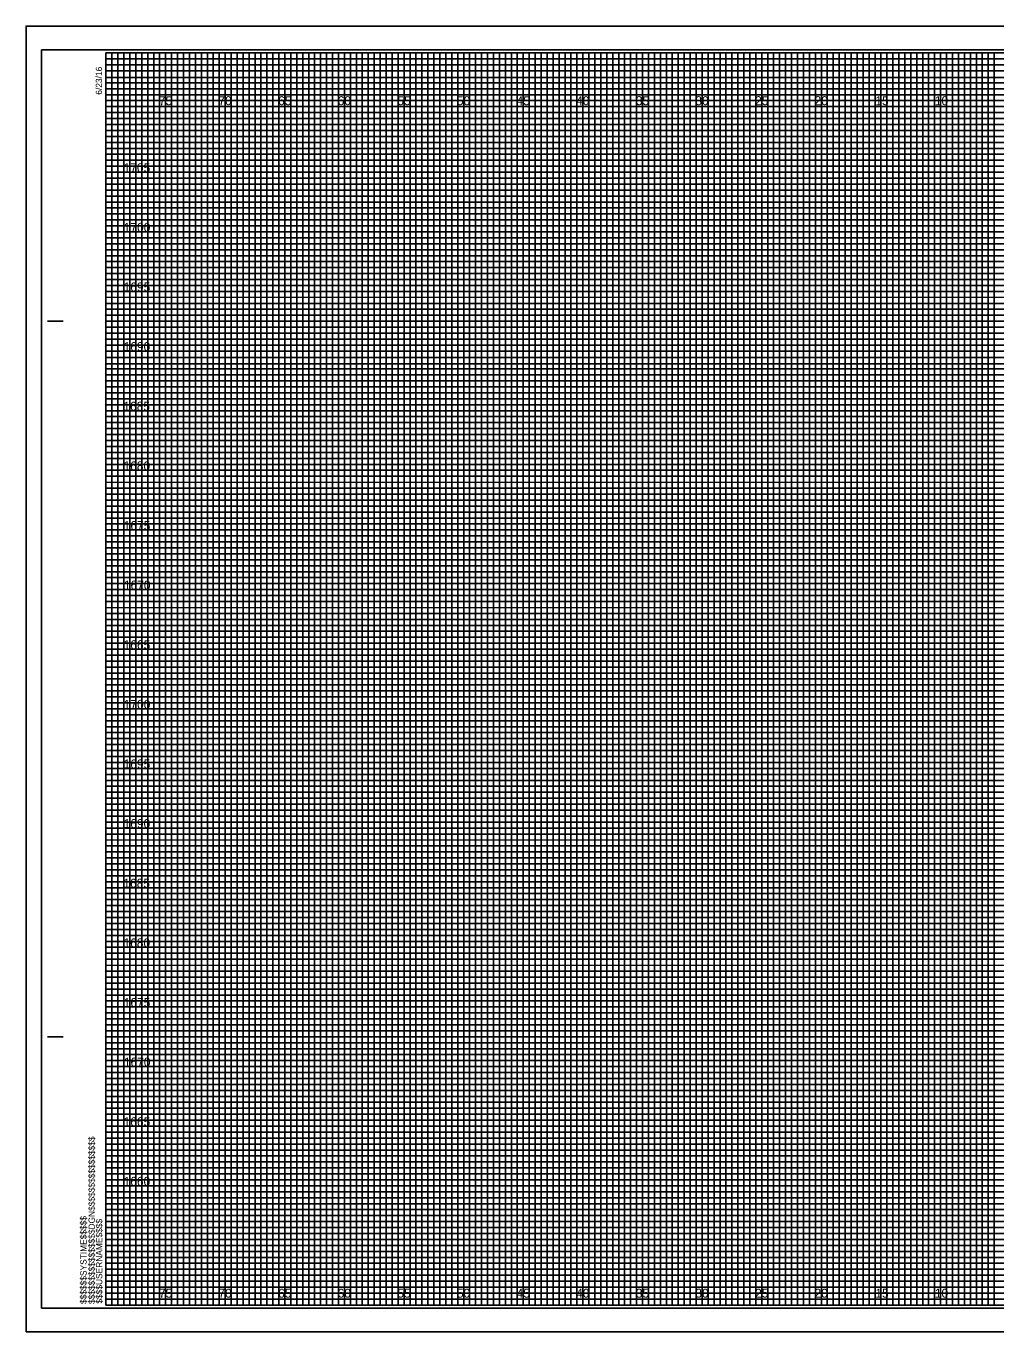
# Model space of a CAD drawing. Extents: x -7 to 162, y -2 to 217.
# Drawn here: x -6.7 to 74.6, y -2.3 to 107.3 of the extents above; entities that cross this region are included whole.
import ezdxf

# ---------------------------------------------------------------- set-up
doc = ezdxf.new("R2010")
doc.units = 0
for name, color, linetype in [('Prop XS Elevation Labels', 7, 'Continuous'), ('Prop XS Offset Labels', 7, 'Continuous'), ('Sheet Cross Section CELL', 7, 'Continuous'), ('Sheet Cross Section Grid Major CELL', 7, 'Continuous'), ('Sheet Cross Section Grid Middle CELL', 7, 'Continuous'), ('Sheet Cross Section Grid Minor 1 CELL', 7, 'Continuous'), ('Sheet Cross Section Grid Minor 2 CELL', 7, 'Continuous'), ('Sheet Cutting Line CELL', 7, 'Continuous'), ('Sheet DOT Grid CELL', 7, 'Continuous'), ('Sheet Plot Border Inside CELL', 7, 'Continuous'), ('Sheet Plot Border Outside CELL', 7, 'Continuous')]:
    doc.layers.add(name, color=color, linetype=linetype)

msp = doc.modelspace()

# ---------------------------------------------------------------- linework, layer by layer
at = {"layer": 'Sheet Cross Section CELL'}
for p, q in [((-4.9, 82.5), (-3.65, 82.5)), ((-4.85, 82.5), (-3.6, 82.5)), ((-4.9, 22.5), (-3.65, 22.5)), ((-4.85, 22.5), (-3.6, 22.5)), ((0, 0), (0, 0)), ((0, 0), (0, 0)), ((0, 0), (0, 0)), ((0, 0), (0, 0)), ((0, 0), (0, 0)), ((0, 0), (0, 0)), ((0, 0), (0, 0))]:
    msp.add_line(p, q, dxfattribs=at)
msp.add_lwpolyline([(160, 105), (0, 105), (0, 0), (160, 0)], close=True, dxfattribs=at)
at = {"layer": 'Sheet Cross Section Grid Major CELL'}
for p, q in [((5, 105), (0, 105)), ((5, 0), (5, 105)), ((15, 105), (10, 105)), ((10, 105), (10, 0)), ((15, 0), (15, 105)), ((25, 105), (20, 105)), ((20, 105), (20, 0)), ((25, 0), (25, 105)), ((35, 105), (30, 105)), ((30, 105), (30, 0)), ((35, 0), (35, 105)), ((45, 105), (40, 105)), ((40, 105), (40, 0)), ((45, 0), (45, 105)), ((55, 105), (50, 105)), ((50, 105), (50, 0)), ((55, 0), (55, 105)), ((65, 105), (60, 105)), ((60, 105), (60, 0)), ((65, 0), (65, 105)), ((75, 105), (70, 105)), ((70, 105), (70, 0)), ((10, 0), (5, 0)), ((20, 0), (15, 0)), ((30, 0), (25, 0)), ((40, 0), (35, 0)), ((50, 0), (45, 0)), ((60, 0), (55, 0)), ((70, 0), (65, 0))]:
    msp.add_line(p, q, dxfattribs=at)
for points in [[(0, 100), (160, 100), (160, 95), (0, 95)], [(0, 90), (160, 90), (160, 85), (0, 85)], [(0, 80), (160, 80), (160, 75), (0, 75)], [(0, 70), (160, 70), (160, 65), (0, 65)], [(0, 60), (160, 60), (160, 55), (0, 55)], [(0, 50), (160, 50), (160, 45), (0, 45)], [(0, 40), (160, 40), (160, 35), (0, 35)], [(0, 30), (160, 30), (160, 25), (0, 25)], [(0, 20), (160, 20), (160, 15), (0, 15)], [(0, 10), (160, 10), (160, 5), (0, 5)]]:
    msp.add_lwpolyline(points, dxfattribs=at)
at = {"layer": 'Sheet Cross Section Grid Middle CELL'}
for points in [[(0, 105), (2.5, 105), (2.5, 0), (7.5, 0), (7.5, 105), (12.5, 105), (12.5, 0), (17.5, 0), (17.5, 105), (22.5, 105), (22.5, 0), (27.5, 0), (27.5, 105), (32.5, 105), (32.5, 0), (37.5, 0), (37.5, 105), (42.5, 105), (42.5, 0), (47.5, 0), (47.5, 105), (52.5, 105), (52.5, 0), (57.5, 0), (57.5, 105), (62.5, 105), (62.5, 0), (67.5, 0), (67.5, 105), (72.5, 105), (72.5, 0), (77.5, 0)], [(0, 102.5), (137.5, 102.5)], [(0, 92.5), (160, 92.5), (160, 97.5), (0, 97.5)], [(0, 82.5), (160, 82.5), (160, 87.5), (0, 87.5)], [(0, 72.5), (160, 72.5), (160, 77.5), (0, 77.5)], [(0, 62.5), (160, 62.5), (160, 67.5), (0, 67.5)], [(0, 52.5), (160, 52.5), (160, 57.5), (0, 57.5)], [(0, 42.5), (160, 42.5), (160, 47.5), (0, 47.5)], [(0, 32.5), (160, 32.5), (160, 37.5), (0, 37.5)], [(0, 22.5), (160, 22.5), (160, 27.5), (0, 27.5)], [(0, 12.5), (160, 12.5), (160, 17.5), (0, 17.5)], [(0, 2.5), (160, 2.5), (160, 7.5), (0, 7.5)]]:
    msp.add_lwpolyline(points, dxfattribs=at)
at = {"layer": 'Sheet Cross Section Grid Minor 1 CELL'}
for p, q in [((0, 104.5), (130, 104.5)), ((130, 103.99), (0, 103.99)), ((0, 103.99), (0, 103.5)), ((0, 103.5), (130, 103.5)), ((130, 102.95), (0, 102.95)), ((0, 102.95), (0, 102)), ((0, 102), (160, 102))]:
    msp.add_line(p, q, dxfattribs=at)
for points in [[(0, 101.5), (135, 101.5), (160, 101.5), (160, 101), (0, 101)], [(0, 100.5), (160, 100.5), (160, 99.5), (0, 99.5)], [(0, 99), (160, 99), (160, 98.5), (0, 98.49)], [(0, 98), (160, 98), (160, 97), (0, 97)], [(0, 96.5), (160, 96.5), (160, 96), (0, 96)], [(0, 95.5), (160, 95.5), (160, 94.5), (0, 94.5)], [(0, 94), (160, 94), (160, 93.5), (0, 93.5)], [(0, 93), (160, 93), (160, 92), (0, 92)], [(0, 91.5), (160, 91.5), (160, 91), (0, 91)], [(0, 90.5), (160, 90.5), (160, 89.5), (0, 89.5)], [(0, 89), (160, 89), (160, 88.5), (0, 88.5)], [(0, 88), (160, 88), (160, 86.98), (160, 86.5), (160, 86), (0, 86)], [(0, 87), (160, 87), (160, 86.5), (0, 86.5)], [(0, 85.5), (160, 85.5), (160, 84.5), (0, 84.52)], [(0, 84.52), (160, 84.5), (160, 84), (0, 84)], [(0, 83.5), (160, 83.5), (160, 83), (0, 83)], [(0, 82), (160, 82), (160, 81.5), (0, 81.5)], [(0, 81), (160, 81), (160, 80.5), (0, 80.5)], [(-0.04, 79.45), (160, 79.45), (160, 78.94), (-0.04, 78.94)], [(0, 78.5), (160, 78.5), (160, 78), (0, 78)], [(0, 77), (160, 77), (160, 76.5), (0, 76.5)], [(0, 76), (160, 76), (160, 75.5), (0, 75.5)], [(0, 74.5), (160, 74.5), (160, 74), (0, 74)], [(0, 73.5), (160, 73.5), (160, 73), (0, 73)], [(0, 72), (160, 72), (160, 71.5), (0, 71.5)], [(0, 71), (160, 71), (160, 70.5), (0, 70.5)], [(0, 69.5), (160, 69.5), (160, 68.99), (0, 69)], [(0, 68.5), (160, 68.5), (160, 68), (0, 68)], [(0, 67), (160, 67), (160, 66.5), (0, 66.5)], [(0, 66), (160, 66), (160, 65.5), (0, 65.5)], [(0, 64.5), (160, 64.5), (160, 64), (0, 64)], [(0, 63.5), (160, 63.5), (160, 63), (0, 63)], [(0, 62), (160, 62), (160, 61.5), (0, 61.5)], [(0, 61), (160, 61), (160, 60.5), (0, 60.5)], [(0, 59.5), (160, 59.5), (160, 59), (0, 59)], [(0, 58.5), (160.03, 58.45), (160, 58), (0, 58)], [(0, 57), (160, 57), (160, 56.5), (0, 56.5)], [(0, 56), (160, 56), (160, 55.5), (0, 55.5)], [(0, 54.5), (160, 54.5), (160, 54), (0, 54)], [(0, 53.5), (160, 53.5), (160, 53), (0, 53)], [(0, 52), (160, 52), (160, 51.5), (0, 51.5)], [(0, 51), (160, 51), (160, 50.5), (0, 50.5)], [(0, 49.5), (160, 49.5), (160, 49), (0, 49)], [(0, 48.5), (160, 48.5), (160, 48), (0, 48)], [(0, 47), (160, 47), (160, 46.5), (0, 46.5)], [(0, 46), (160, 46), (160, 45.5), (0, 45.5)], [(0, 44.5), (160, 44.5), (160, 44), (0, 44)], [(0, 43.5), (160, 43.5), (160, 43), (0, 43)], [(0, 42), (160, 42), (160, 41.5), (0, 41.5)], [(0, 41), (160, 41), (160, 40.5), (0, 40.5)], [(0, 39.5), (160, 39.5), (160, 38.99), (0, 39)], [(0, 38.5), (160, 38.5), (160, 38), (0, 38)], [(0, 37), (160, 37), (160, 36.5), (0, 36.5)], [(0, 36), (160, 36), (160, 35.5), (0, 35.5)], [(0, 34.5), (160, 34.5), (160, 34), (0, 34)], [(0, 33.5), (160, 33.5), (160, 33), (0, 33)], [(0, 32), (160, 32), (160, 31.5), (0, 31.5)], [(0, 31), (160, 31), (160, 30.5), (0, 30.5)], [(0, 29.5), (160, 29.5), (160, 29), (0, 29)], [(0, 28.5), (160.03, 28.46), (160, 28), (0, 28)], [(0, 27), (160, 27), (160, 26.5), (0, 26.5)], [(0, 26), (160, 26), (160, 25.5), (0, 25.5)], [(0, 24.5), (160, 24.5), (160, 24), (0, 24)], [(0, 23.5), (160, 23.5), (160, 23), (0, 23)], [(0, 22), (160, 22), (160, 21.5), (0, 21.5)], [(0, 21), (160, 21), (160, 20.5), (0, 20.5)], [(0, 19.5), (160, 19.5), (160, 19), (0, 19)], [(0, 18.5), (160, 18.5), (160, 18), (0, 18)], [(0, 17), (160, 17), (160, 16.5), (0, 16.5)], [(0, 16), (160, 16), (160, 15.5), (0, 15.5)], [(0, 14.5), (160, 14.5), (160, 14), (0, 14)], [(0, 13.5), (160, 13.5), (160, 13), (0, 13)], [(0, 12), (160, 12), (160, 11.5), (0, 11.5)], [(0, 11), (160, 11), (160, 10.5), (0, 10.5)], [(0, 9.5), (160, 9.5), (160, 9), (0, 9)], [(0, 8.5), (160, 8.5), (160, 8), (0, 8)], [(0, 7), (160, 7), (160, 6.5), (0, 6.5)], [(0, 6), (160, 6), (160, 5.5), (0, 5.5)], [(0, 4.5), (160, 4.5), (160, 4), (0, 4)], [(0, 3.5), (160, 3.5), (160, 3), (0, 3)], [(0, 2), (160, 2), (160, 1.5), (0, 1.5)], [(0, 1), (160, 1), (160, 0.5), (0, 0.5)]]:
    msp.add_lwpolyline(points, dxfattribs=at)
at = {"layer": 'Sheet Cross Section Grid Minor 2 CELL'}
for points in [[(0, 0), (0.5, 0), (0.5, 105), (1, 105), (1, 0)], [(1, 0), (1.5, 0), (1.5, 105), (2, 105), (2, 0)], [(2.5, 0), (3, 0), (3, 105), (3.5, 105), (3.5, 0)], [(3.5, 0), (4, 0), (4, 105), (4.5, 105), (4.5, 0)], [(5, 0), (5.5, 0), (5.5, 105), (6, 105), (6, 0)], [(6, 0), (6.5, 0), (6.5, 105), (7, 105), (7, 0)], [(7.5, 0), (8, 0), (8, 105), (8.5, 105), (8.5, 0)], [(8.5, 0), (9, 0), (9, 105), (9.5, 105), (9.5, 0)], [(10, 0), (10.5, 0), (10.5, 105), (11, 105), (11, 0)], [(11, 0), (11.5, 0), (11.5, 105), (12, 105), (12, 0)], [(12.5, 0), (13, 0), (13, 105), (13.5, 105), (13.5, 0)], [(13.5, 0), (14, 0), (14, 105), (14.5, 105), (14.5, 0)], [(15, 0), (15.5, 0), (15.5, 105), (16, 105), (16, 0)], [(16, 0), (16.5, 0), (16.5, 105), (17, 105), (17, 0)], [(17.5, 0), (18, 0), (18, 105), (18.5, 105), (18.5, 0)], [(18.5, 0), (19, 0), (19, 105), (19.5, 105), (19.5, 0)], [(20, 0), (20.5, 0), (20.5, 105), (21, 105), (21, 0)], [(21, 0), (21.5, 0), (21.5, 105), (22, 105), (22, 0)], [(22.5, 0), (23, 0), (23, 105), (23.5, 105), (23.5, 0)], [(23.5, 0), (24, 0), (24, 105), (24.5, 105), (24.5, 0)], [(25, 0), (25.5, 0), (25.5, 105), (26, 105), (26, 0)], [(26, 0), (26.5, 0), (26.5, 105), (27, 105), (27, 0)], [(27.5, 0), (28, 0), (28, 105), (28.5, 105), (28.5, 0)], [(28.5, 0), (29, 0), (29, 105), (29.5, 105), (29.5, 0)], [(30, 0), (30.5, 0), (30.5, 105), (31, 105), (31, 0)], [(31, 0), (31.5, 0), (31.5, 105), (32, 105), (32, 0)], [(32.5, 0), (33, 0), (33, 105), (33.5, 105), (33.5, 0)], [(33.5, 0), (34, 0), (34, 105), (34.5, 105), (34.5, 0)], [(35, 0), (35.5, 0), (35.5, 105), (36, 105), (36, 0)], [(36, 0), (36.5, 0), (36.5, 105), (37, 105), (37, 0)], [(37.5, 0), (38, 0), (38, 105), (38.5, 105), (38.5, 0)], [(38.5, 0), (39, 0), (39, 105), (39.5, 105), (39.5, 0)], [(40, 0), (40.5, 0), (40.5, 105), (41, 105), (41, 0)], [(41, 0), (41.5, 0), (41.5, 105), (42, 105), (42, 0)], [(42.5, 0), (43, 0), (43, 105), (43.5, 105), (43.5, 0)], [(43.5, 0), (44, 0), (44, 105), (44.5, 105), (44.5, 0)], [(45, 0), (45.5, 0), (45.5, 105), (46, 105), (46, 0)], [(46, 0), (46.5, 0), (46.5, 105), (47, 105), (47, 0)], [(47.5, 0), (48, 0), (48, 105), (48.5, 105), (48.5, 0)], [(48.5, 0), (49, 0), (49, 105), (49.5, 105), (49.5, 0)], [(50, 0), (50.5, 0), (50.5, 105), (51, 105), (51, 0)], [(51, 0), (51.5, 0), (51.5, 105), (52, 105), (52, 0)], [(52.5, 0), (53, 0), (53, 105), (53.5, 105), (53.5, 0)], [(53.5, 0), (54, 0), (54, 105), (54.5, 105), (54.5, 0)], [(55, 0), (55.5, 0), (55.5, 105), (56, 105), (56, 0)], [(56, 0), (56.5, 0), (56.5, 105), (57, 105), (57, 0)], [(57.5, 0), (58, 0), (58, 105), (58.5, 105), (58.5, 0)], [(58.5, 0), (59, 0), (59, 105), (59.5, 105), (59.5, 0)], [(60, 0), (60.5, 0), (60.5, 105), (61, 105), (61, 0)], [(61, 0), (61.5, 0), (61.5, 105), (62, 105), (62, 0)], [(62.5, 0), (63, 0), (63, 105), (63.5, 105), (63.5, 0)], [(63.5, 0), (64, 0), (64, 105), (64.5, 105), (64.5, 0)], [(65, 0), (65.5, 0), (65.5, 105), (66, 105), (66, 0)], [(66, 0), (66.5, 0), (66.5, 105), (67, 105), (67, 0)], [(67.5, 0), (68, 0), (68, 105), (68.5, 105), (68.5, 0)], [(68.5, 0), (69, 0), (69, 105), (69.5, 105), (69.5, 0)], [(70, 0), (70.5, 0), (70.5, 105), (71, 105), (71, 0)], [(71, 0), (71.5, 0), (71.5, 105), (72, 105), (72, 0)], [(72.5, 0), (73, 0), (73, 105), (73.5, 105), (73.5, 0)], [(73.5, 0), (74, 0), (74, 105), (74.5, 105), (74.5, 0)]]:
    msp.add_lwpolyline(points, dxfattribs=at)
at = {"layer": 'Sheet Cutting Line CELL'}
for p, q in [((161.65, 107.25), (-6.7, 107.25)), ((-6.7, 107.25), (-6.7, -2.25)), ((-6.7, -2.25), (161.65, -2.25))]:
    msp.add_line(p, q, dxfattribs=at)
at = {"layer": 'Sheet DOT Grid CELL'}
for p, q in [((5, 0), (5, 105)), ((10, 0), (10, 105)), ((15, 0), (15, 105)), ((20, 0), (20, 105)), ((25, 0), (25, 105)), ((30, 0), (30, 105)), ((35, 0), (35, 105)), ((40, 0), (40, 105)), ((45, 0), (45, 105)), ((50, 0), (50, 105)), ((55, 0), (55, 105)), ((60, 0), (60, 105)), ((65, 0), (65, 105)), ((70, 0), (70, 105)), ((0, 100), (160, 100)), ((0, 95), (160, 95)), ((0, 90), (160, 90)), ((0, 85), (160, 85)), ((0, 80), (160, 80)), ((0, 75), (160, 75)), ((0, 70), (160, 70)), ((0, 65), (160, 65)), ((0, 60), (160, 60)), ((0, 55), (160, 55)), ((0, 50), (160, 50)), ((0, 45), (160, 45)), ((0, 40), (160, 40)), ((0, 35), (160, 35)), ((0, 30), (160, 30)), ((0, 25), (160, 25)), ((0, 20), (160, 20)), ((0, 15), (160, 15)), ((0, 10), (160, 10)), ((0, 5), (160, 5))]:
    msp.add_line(p, q, dxfattribs=at)
at = {"layer": 'Sheet Plot Border Inside CELL'}
msp.add_lwpolyline([(-5.4, -0.25), (161.2, -0.25), (161.2, 105.25), (-5.4, 105.25)], close=True, dxfattribs=at)
at = {"layer": 'Sheet Plot Border Outside CELL'}
msp.add_lwpolyline([(-6.7, -2.25), (161.65, -2.25), (161.65, 107.25), (-6.7, 107.25)], close=True, dxfattribs=at)

# ---------------------------------------------------------------- texts
at = {"layer": 'Prop XS Elevation Labels'}
for s, p in [('1705', (1.48, 95)), ('1700', (1.49, 90)), ('1695', (1.48, 85)), ('1690', (1.48, 80)), ('1685', (1.46, 75)), ('1680', (1.47, 70)), ('1675', (1.49, 65)), ('1670', (1.5, 60)), ('1665', (1.48, 55)), ('1700', (1.49, 50)), ('1695', (1.48, 45)), ('1690', (1.48, 40)), ('1685', (1.46, 35)), ('1680', (1.47, 30)), ('1675', (1.49, 25)), ('1670', (1.5, 20)), ('1665', (1.48, 15)), ('1660', (1.48, 10))]:
    msp.add_text(s, height=0.75, dxfattribs=at).set_placement(p)
at = {"layer": 'Prop XS Offset Labels'}
for s, p in [('75', (4.44, 100.62)), ('70', (9.43, 100.62)), ('65', (14.44, 100.62)), ('60', (19.43, 100.62)), ('55', (24.44, 100.62)), ('50', (29.43, 100.62)), ('45', (34.44, 100.62)), ('40', (39.43, 100.62)), ('35', (44.44, 100.62)), ('30', (49.43, 100.62)), ('25', (54.44, 100.62)), ('20', (59.43, 100.62)), ('15', (64.53, 100.62)), ('10', (69.52, 100.62)), ('75', (4.44, 0.62)), ('70', (9.43, 0.62)), ('65', (14.44, 0.62)), ('60', (19.43, 0.62)), ('55', (24.44, 0.62)), ('50', (29.43, 0.62)), ('45', (34.44, 0.62)), ('40', (39.43, 0.62)), ('35', (44.44, 0.62)), ('30', (49.43, 0.62)), ('25', (54.44, 0.62)), ('20', (59.43, 0.62)), ('15', (64.53, 0.62)), ('10', (69.52, 0.62))]:
    msp.add_text(s, height=0.75, dxfattribs=at).set_placement(p)
at = {"layer": 'Sheet Cross Section CELL'}
for s, p in [('6/23/16', (-0.33, 101.5)), ('$$$$$$$$$$$$$$$$DGN$$$$$$$$$$$$$$$$', (-0.94, 0.09)), ('$$$$$$SYSTIME$$$$$', (-1.63, 0.09)), ('$$$$USERNAME$$$$', (-0.31, 0.12))]:
    msp.add_text(s, height=0.525, rotation=90, dxfattribs=at).set_placement(p)

doc.saveas('drawing.dxf')
